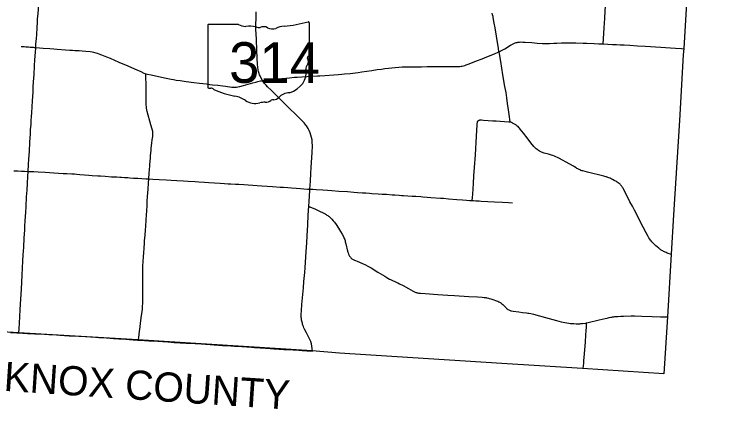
# Model space of a CAD drawing. Extents: x 1815539 to 1947826, y 273303 to 993194.
# Drawn here: x 1905397 to 1929509, y 852982 to 866502 of the extents above; entities that cross this region are included whole.
import ezdxf

# ---------------------------------------------------------------- set-up
doc = ezdxf.new("R2010")
doc.units = 0
for name, color, linetype in [('GM_X_Adjacent_County_Text', 7, 'Continuous'), ('GM_X_County', 7, 'Continuous'), ('GM_X_County_Road', 7, 'Continuous'), ('GM_X_State_Route', 7, 'Continuous'), ('GM_X_Township_Road', 7, 'Continuous'), ('SC_Shading3', 7, 'Continuous')]:
    doc.layers.add(name, color=color, linetype=linetype)

msp = doc.modelspace()

# ---------------------------------------------------------------- linework, layer by layer
at = {"layer": 'GM_X_County'}
msp.add_lwpolyline([(1929509, 885709), (1929483, 885147), (1929313, 880637), (1929312, 880613), (1928987, 876105), (1928954, 875572), (1928932, 875213), (1928849, 873883), (1928341, 865325), (1928314, 865105), (1928189, 862861), (1927988, 859624), (1927907, 858279), (1927777, 856135), (1927658, 854184), (1924873, 854361), (1922111, 854537), (1916549, 854893), (1915609, 854967), (1909640, 855342), (1905546, 855583), (1900992, 855867)], dxfattribs=at)
at = {"layer": 'GM_X_County_Road'}
for points in [[(1925577, 865482), (1925590, 865650), (1925613, 866026), (1925635, 866353), (1925651, 866614), (1925660, 866761), (1925672, 866958), (1925687, 867219), (1925706, 867530), (1925716, 867693), (1925727, 867873), (1925743, 868135), (1925765, 868478), (1925780, 868739), (1925793, 868952), (1925813, 869262), (1925827, 869476)], [(1906139, 865355), (1906148, 865479), (1906161, 865659), (1906173, 865815), (1906185, 866019), (1906199, 866231), (1906205, 866329), (1906219, 866526), (1906230, 866675), (1906238, 866822), (1906244, 866918), (1906256, 867164), (1906266, 867327), (1906272, 867458), (1906276, 867540), (1906279, 867576)], [(1922010, 865208), (1922119, 865267), (1922208, 865315), (1922405, 865433), (1922477, 865473), (1922535, 865502), (1922565, 865515), (1922596, 865526), (1922628, 865534), (1922660, 865540), (1922710, 865545), (1922759, 865547), (1922825, 865545), (1922907, 865541), (1923136, 865524), (1923316, 865511), (1923496, 865498), (1923611, 865492), (1923682, 865490), (1923742, 865492), (1923890, 865501), (1923988, 865506), (1924147, 865514), (1924152, 865514), (1924284, 865520), (1924415, 865522), (1924514, 865522), (1924645, 865518), (1924891, 865509), (1925022, 865505), (1925268, 865495), (1925429, 865488), (1925577, 865482)], [(1925577, 865482), (1925894, 865465), (1926038, 865458), (1926161, 865452), (1926248, 865446), (1926301, 865444), (1926495, 865433), (1926757, 865417), (1927018, 865401), (1927555, 865366), (1927718, 865355), (1928054, 865333), (1928259, 865318), (1928358, 865310)], [(1905878, 861113), (1905895, 861355), (1905906, 861535), (1905921, 861797), (1905939, 862119), (1905957, 862403), (1905965, 862534), (1905977, 862730), (1905986, 862861), (1905993, 862992), (1906002, 863123), (1906029, 863532), (1906038, 863679), (1906046, 863827), (1906056, 864007), (1906068, 864187), (1906081, 864432), (1906084, 864514), (1906092, 864645), (1906097, 864743), (1906108, 864923), (1906119, 865070), (1906129, 865201), (1906138, 865332), (1906139, 865355)], [(1920339, 864710), (1920454, 864709), (1920601, 864708), (1920666, 864710), (1920715, 864715), (1920747, 864720), (1920795, 864730), (1920842, 864743), (1920889, 864759), (1920950, 864782), (1921102, 864843), (1921240, 864897), (1921428, 864970), (1921591, 865034), (1921851, 865137), (1922006, 865206), (1922010, 865208)], [(1913907, 864224), (1913965, 864232), (1914021, 864238), (1914567, 864294), (1914828, 864323), (1915008, 864339), (1915090, 864346), (1915254, 864354), (1915614, 864373), (1915794, 864385), (1915876, 864390), (1916040, 864402), (1916351, 864423), (1916515, 864435), (1916629, 864444), (1916711, 864451), (1916907, 864469), (1917004, 864480), (1917183, 864504), (1917313, 864522), (1917476, 864546), (1917654, 864573), (1917833, 864599), (1917979, 864620), (1918093, 864635), (1918223, 864653), (1918337, 864666), (1918452, 864678), (1918583, 864687), (1918697, 864693), (1918845, 864697), (1919058, 864700), (1919190, 864700), (1919354, 864700), (1919551, 864703), (1919879, 864707), (1920043, 864711), (1920191, 864711), (1920339, 864710)], [(1905393, 861139), (1905528, 861131), (1905646, 861126), (1905759, 861120), (1905878, 861113)], [(1905558, 855587), (1905569, 855740), (1905581, 855920), (1905607, 856378), (1905629, 856755), (1905638, 856902), (1905649, 857098), (1905659, 857311), (1905673, 857573), (1905685, 857803), (1905701, 858048), (1905712, 858247), (1905728, 858523), (1905746, 858834), (1905761, 859112), (1905769, 859243), (1905779, 859424), (1905789, 859571), (1905796, 859718), (1905807, 859898), (1905828, 860242), (1905835, 860356), (1905841, 860471), (1905854, 860717), (1905867, 860946), (1905878, 861110), (1905878, 861113)], [(1905878, 861113), (1905907, 861112), (1906070, 861106), (1906219, 861099), (1906460, 861085), (1906607, 861075), (1906762, 861065), (1906918, 861053), (1907080, 861046), (1907206, 861041), (1907376, 861036), (1907470, 861029), (1907546, 861019), (1907650, 861006), (1907804, 860992), (1907963, 860983), (1908077, 860976), (1908264, 860965), (1908355, 860959), (1908522, 860947), (1908732, 860932), (1908922, 860924), (1909017, 860919), (1909081, 860914), (1909176, 860908), (1909292, 860901), (1909358, 860897), (1909485, 860888), (1909639, 860879), (1909776, 860872), (1909916, 860863), (1910012, 860858)], [(1910012, 860858), (1910156, 860849), (1910364, 860840), (1910612, 860828), (1910776, 860818), (1910972, 860805), (1911201, 860789), (1911366, 860779), (1911605, 860766), (1911723, 860758), (1911923, 860745), (1912071, 860735), (1912453, 860712), (1912603, 860701), (1912736, 860694), (1912822, 860688), (1912986, 860680), (1913100, 860673), (1913264, 860663), (1913411, 860653), (1913886, 860622), (1914246, 860597), (1914508, 860579), (1914622, 860571), (1914770, 860562), (1914904, 860551), (1915061, 860538), (1915211, 860528), (1915321, 860518), (1915444, 860511), (1915533, 860508)], [(1915496, 859920), (1915526, 859907), (1915720, 859818), (1915883, 859740), (1915958, 859705), (1916005, 859683), (1916050, 859660), (1916069, 859649), (1916089, 859638), (1916116, 859622), (1916141, 859606), (1916167, 859587), (1916192, 859566), (1916217, 859544), (1916242, 859522), (1916283, 859480), (1916332, 859427), (1916353, 859403), (1916374, 859376), (1916431, 859295), (1916510, 859171), (1916579, 859059), (1916639, 858962), (1916678, 858889), (1916697, 858848), (1916710, 858818), (1916723, 858783), (1916734, 858744), (1916745, 858704), (1916760, 858640), (1916819, 858386), (1916829, 858353), (1916837, 858323), (1916855, 858277), (1916865, 858257), (1916877, 858234), (1916890, 858214), (1916906, 858191), (1916921, 858174), (1916937, 858158), (1916973, 858126), (1917013, 858099), (1917037, 858085), (1917059, 858075), (1917093, 858061), (1917146, 858039), (1917329, 857967), (1917434, 857921), (1917521, 857875), (1917634, 857808), (1917857, 857669), (1918095, 857523), (1918199, 857462), (1918259, 857429), (1918295, 857410), (1918336, 857390), (1918382, 857368), (1918421, 857351), (1918463, 857334), (1918507, 857315), (1918549, 857296), (1918603, 857268), (1918721, 857208), (1918908, 857105), (1919066, 857019), (1919110, 856995), (1919139, 856983), (1919161, 856973), (1919184, 856966), (1919207, 856960), (1919232, 856955), (1919263, 856950), (1919287, 856947), (1919324, 856942), (1919476, 856929), (1919918, 856902), (1920262, 856879), (1920490, 856865), (1920981, 856834), (1921276, 856817), (1921437, 856807), (1921499, 856802), (1921533, 856798), (1921557, 856795), (1921582, 856790), (1921608, 856784), (1921647, 856775), (1921678, 856768), (1921731, 856751), (1921803, 856727), (1921926, 856681), (1921967, 856666), (1922003, 856651), (1922024, 856641), (1922047, 856629), (1922067, 856615), (1922089, 856602), (1922110, 856586), (1922139, 856559), (1922186, 856512), (1922231, 856465), (1922255, 856442), (1922272, 856425), (1922287, 856411), (1922302, 856401), (1922316, 856390), (1922347, 856372), (1922368, 856361), (1922389, 856351), (1922412, 856342), (1922435, 856336), (1922499, 856324), (1922691, 856301), (1922818, 856287), (1922957, 856271), (1922997, 856266), (1923035, 856261), (1923095, 856250), (1923191, 856227), (1923602, 856114), (1923981, 856009), (1924139, 855967), (1924268, 855939), (1924334, 855928), (1924397, 855919), (1924462, 855912), (1924511, 855907), (1924578, 855902), (1924658, 855899), (1924740, 855899), (1924776, 855900), (1924815, 855902), (1924870, 855907), (1924983, 855923), (1925012, 855929)], [(1925012, 855929), (1925061, 855938), (1925443, 856031), (1925650, 856081), (1925712, 856094), (1925780, 856110), (1925843, 856122), (1925867, 856126), (1925899, 856132), (1925940, 856138), (1925979, 856143), (1926013, 856146), (1926082, 856151), (1926181, 856157), (1926279, 856161), (1926541, 856170), (1926654, 856169), (1926907, 856160), (1927262, 856148), (1927540, 856139), (1927711, 856134), (1927729, 856133), (1927751, 856132), (1927784, 856130)], [(1905275, 855603), (1905405, 855595), (1905488, 855590), (1905558, 855587)]]:
    msp.add_lwpolyline(points, dxfattribs=at)
at = {"layer": 'GM_X_State_Route'}
msp.add_lwpolyline([(1915617, 854964), (1915613, 855047), (1915603, 855128), (1915585, 855208), (1915561, 855287), (1915531, 855363), (1915489, 855453), (1915420, 855583), (1915351, 855713), (1915329, 855764), (1915310, 855807), (1915294, 855851), (1915282, 855888), (1915273, 855919), (1915262, 855958), (1915249, 856019), (1915245, 856044), (1915240, 856078), (1915237, 856114), (1915234, 856152), (1915232, 856217), (1915239, 856348), (1915260, 856559), (1915279, 856788), (1915309, 857131), (1915327, 857343), (1915353, 857652), (1915365, 857816), (1915404, 858372), (1915421, 858666), (1915435, 858912), (1915456, 859288), (1915476, 859615), (1915496, 859920), (1915507, 860090), (1915530, 860466), (1915533, 860508), (1915549, 860777), (1915564, 861039), (1915578, 861251), (1915606, 861759), (1915615, 861988), (1915614, 862119), (1915605, 862201), (1915589, 862281), (1915567, 862361), (1915539, 862438), (1915506, 862514), (1915467, 862586), (1915415, 862670), (1915394, 862700), (1915371, 862730), (1915331, 862777), (1915301, 862810), (1915266, 862847), (1915163, 862951), (1915022, 863088), (1914858, 863249), (1914692, 863408), (1914201, 863891), (1914076, 864015), (1914028, 864065), (1913974, 864126), (1913926, 864192), (1913907, 864224), (1913893, 864248), (1913848, 864336), (1913822, 864391), (1913809, 864425), (1913795, 864464), (1913783, 864502), (1913772, 864539), (1913763, 864582), (1913755, 864620), (1913749, 864662), (1913745, 864696), (1913740, 864760), (1913716, 865251), (1913699, 865644), (1913684, 865988), (1913681, 866151), (1913685, 866348), (1913693, 866577)], dxfattribs=at)
at = {"layer": 'GM_X_Township_Road'}
for points in [[(1922010, 865208), (1922009, 865215), (1921988, 865321), (1921920, 865751), (1921874, 866026), (1921846, 866187), (1921813, 866381), (1921805, 866420), (1921792, 866478), (1921774, 866538)], [(1905640, 865396), (1905666, 865393)], [(1905666, 865393), (1905673, 865392), (1905700, 865389), (1905737, 865387), (1905799, 865383), (1905889, 865377), (1905948, 865374), (1905998, 865370), (1906052, 865364), (1906081, 865362), (1906103, 865360), (1906121, 865358), (1906131, 865356), (1906139, 865355)], [(1906139, 865355), (1906388, 865333), (1906617, 865318), (1906764, 865309), (1906878, 865302), (1907155, 865282), (1907302, 865272), (1907400, 865265), (1907482, 865260), (1907629, 865250), (1907727, 865242), (1907857, 865230), (1908004, 865216), (1908069, 865207), (1908118, 865198), (1908197, 865178), (1908244, 865163), (1908306, 865141), (1908397, 865104), (1908564, 865036), (1908685, 864987), (1908836, 864923), (1908986, 864858), (1909122, 864802), (1909213, 864763), (1909393, 864684), (1909527, 864624), (1909737, 864531), (1909844, 864484), (1909910, 864456)], [(1922392, 862807), (1922355, 863065), (1922333, 863228), (1922304, 863439), (1922277, 863634), (1922250, 863812), (1922214, 864022), (1922146, 864426), (1922067, 864878), (1922021, 865137), (1922010, 865208)], [(1909921, 863493), (1909921, 863590), (1909922, 863719), (1909921, 863913), (1909919, 864120), (1909912, 864312), (1909910, 864456)], [(1909910, 864456), (1909968, 864443), (1910088, 864417), (1910246, 864382), (1910400, 864349), (1910552, 864319), (1910778, 864273), (1910858, 864258), (1910955, 864242), (1911085, 864225), (1911296, 864197), (1911556, 864161), (1911751, 864138), (1911864, 864122), (1911985, 864108), (1912105, 864095), (1912197, 864083), (1912374, 864063), (1912548, 864042), (1912645, 864030), (1912856, 864000), (1912905, 863996), (1912937, 863995), (1912969, 863995), (1913018, 864000), (1913066, 864009), (1913129, 864025), (1913255, 864060), (1913572, 864145), (1913682, 864176), (1913752, 864194), (1913791, 864202), (1913837, 864212), (1913877, 864219), (1913907, 864224)], [(1910045, 861283), (1910049, 861340), (1910058, 861464), (1910068, 861570), (1910075, 861651), (1910083, 861753), (1910091, 861836), (1910099, 861907), (1910115, 862082), (1910132, 862197), (1910146, 862309), (1910154, 862398), (1910153, 862439), (1910146, 862482), (1910122, 862560), (1910078, 862713), (1909959, 863171), (1909932, 863283), (1909923, 863440), (1909922, 863456), (1909921, 863493)], [(1921094, 860120), (1921104, 860216), (1921112, 860330), (1921135, 860705), (1921152, 860966), (1921171, 861244), (1921201, 861684), (1921241, 862320), (1921263, 862713), (1921266, 862758), (1921267, 862772), (1921269, 862789), (1921271, 862800), (1921272, 862806), (1921274, 862813), (1921276, 862819), (1921279, 862826), (1921285, 862834), (1921290, 862841), (1921295, 862846), (1921300, 862851), (1921307, 862857), (1921313, 862861), (1921321, 862865), (1921328, 862868), (1921335, 862871), (1921343, 862874), (1921351, 862876), (1921358, 862877), (1921368, 862878), (1921376, 862879), (1921388, 862879), (1921409, 862878), (1921474, 862874), (1921799, 862849), (1921914, 862841), (1922045, 862833), (1922351, 862813), (1922364, 862812), (1922377, 862810), (1922392, 862807)], [(1927917, 858265), (1927841, 858291), (1927772, 858318), (1927735, 858334), (1927650, 858375), (1927621, 858390), (1927590, 858407), (1927565, 858422), (1927540, 858438), (1927523, 858451), (1927481, 858484), (1927431, 858527), (1927383, 858570), (1927318, 858631), (1927277, 858671), (1927248, 858701), (1927222, 858732), (1927199, 858761), (1927172, 858797), (1927143, 858843), (1927121, 858881), (1927050, 859011), (1926850, 859399), (1926753, 859589), (1926647, 859793), (1926578, 859922), (1926497, 860072), (1926420, 860216), (1926287, 860480), (1926258, 860538), (1926244, 860564), (1926232, 860584), (1926221, 860602), (1926206, 860623), (1926197, 860635), (1926187, 860647), (1926176, 860658), (1926160, 860675), (1926144, 860689), (1926127, 860703), (1926111, 860714), (1926094, 860725), (1926058, 860749), (1926032, 860765), (1925959, 860806), (1925897, 860838), (1925857, 860858), (1925813, 860879), (1925767, 860897), (1925733, 860910), (1925690, 860925), (1925665, 860933), (1925596, 860952), (1925038, 861090), (1924878, 861129), (1924845, 861140), (1924816, 861150), (1924783, 861163), (1924756, 861176), (1924713, 861198), (1924677, 861218), (1924649, 861235), (1924599, 861266), (1924557, 861291), (1924415, 861373), (1924085, 861556), (1924012, 861593), (1923955, 861619), (1923906, 861639), (1923859, 861656), (1923813, 861671), (1923702, 861703), (1923561, 861745), (1923469, 861778), (1923423, 861797), (1923397, 861811), (1923366, 861829), (1923336, 861849), (1923313, 861867), (1923285, 861890), (1923263, 861910), (1923208, 861970), (1923104, 862098), (1922971, 862264), (1922851, 862421), (1922739, 862562), (1922709, 862598), (1922685, 862623), (1922662, 862647), (1922637, 862669), (1922618, 862684), (1922598, 862699), (1922581, 862710), (1922558, 862724), (1922539, 862735), (1922520, 862745), (1922472, 862771), (1922440, 862787), (1922420, 862796), (1922407, 862801), (1922392, 862807)], [(1910012, 860858), (1910014, 860883), (1910026, 861029), (1910039, 861193), (1910045, 861283)], [(1909805, 856847), (1909805, 856849), (1909810, 857145), (1909813, 857342), (1909811, 857463), (1909811, 857571), (1909809, 857667), (1909807, 857752), (1909807, 857794), (1909809, 857855), (1909810, 857887), (1909819, 858017), (1909833, 858197), (1909843, 858328), (1909854, 858492), (1909864, 858655), (1909870, 858737), (1909878, 858835), (1909884, 858917), (1909898, 859114), (1909906, 859228), (1909922, 859457), (1909933, 859621), (1909943, 859769), (1909952, 859943), (1909961, 860092), (1909971, 860256), (1909979, 860385), (1909985, 860504), (1910000, 860707), (1910012, 860858)], [(1915533, 860508), (1915562, 860508), (1915627, 860506), (1915741, 860499), (1915970, 860484), (1916134, 860473), (1916281, 860463), (1916527, 860443), (1916822, 860422), (1917035, 860406), (1917166, 860396), (1917329, 860383), (1917444, 860376), (1917575, 860369), (1917657, 860364), (1917866, 860349), (1918006, 860340), (1918151, 860330), (1918347, 860316), (1918444, 860310), (1918591, 860299), (1918673, 860294), (1918739, 860289), (1918886, 860280), (1919033, 860271), (1919164, 860262), (1919327, 860251), (1919403, 860246), (1919547, 860236), (1919678, 860226), (1920005, 860200), (1920109, 860193), (1920283, 860178), (1920562, 860157), (1920758, 860142), (1920892, 860132), (1921004, 860124), (1921094, 860120)], [(1921094, 860120), (1921133, 860117), (1921215, 860112), (1921275, 860107), (1921332, 860103), (1921401, 860100), (1921858, 860078), (1922127, 860060), (1922335, 860045), (1922475, 860036)], [(1909702, 855702), (1909716, 855804), (1909728, 855902), (1909754, 856097), (1909764, 856178), (1909780, 856309), (1909791, 856407), (1909800, 856505), (1909804, 856587), (1909805, 856669), (1909804, 856718), (1909805, 856847)], [(1924892, 854363), (1924910, 854552), (1924919, 854646), (1924928, 854728), (1924951, 855019), (1924960, 855121), (1924964, 855169), (1924968, 855247), (1924971, 855299), (1924981, 855480), (1925001, 855692), (1925006, 855752), (1925010, 855823), (1925010, 855849), (1925011, 855905), (1925012, 855929)], [(1905558, 855587), (1905695, 855578), (1905859, 855569), (1906104, 855555), (1906437, 855537), (1906585, 855530), (1906699, 855525), (1906856, 855514), (1906960, 855507), (1907282, 855488), (1907610, 855470), (1907839, 855457), (1908019, 855447), (1908182, 855436), (1908297, 855429), (1908559, 855411), (1908689, 855403), (1908804, 855396), (1908984, 855385), (1909229, 855370), (1909474, 855353), (1909637, 855341), (1909654, 855341)], [(1909654, 855341), (1909658, 855364), (1909667, 855429), (1909694, 855641), (1909702, 855702)], [(1909654, 855341), (1909719, 855337), (1909866, 855329), (1910014, 855319), (1910178, 855310), (1910325, 855298), (1910497, 855288), (1910668, 855276), (1910887, 855260), (1911090, 855247), (1911290, 855235), (1911596, 855218), (1911807, 855205), (1911953, 855197), (1912117, 855186), (1912256, 855177), (1912403, 855167), (1912534, 855157), (1912681, 855148), (1912943, 855131), (1913205, 855114), (1913368, 855104), (1913532, 855092), (1913630, 855086), (1913728, 855080), (1913827, 855075), (1913908, 855070), (1914006, 855063), (1914105, 855057), (1914170, 855052), (1914301, 855044), (1914480, 855032), (1914639, 855021), (1914808, 855012), (1914961, 855002), (1915152, 854990), (1915266, 854983), (1915430, 854973), (1915512, 854968), (1915617, 854964)]]:
    msp.add_lwpolyline(points, dxfattribs=at)
at = {"layer": 'SC_Shading3'}
for p, q in [((1913085, 866148), (1912066, 866148)), ((1915512, 865095), (1915512, 866200)), ((1912031, 866111), (1912031, 863998)), ((1915512, 865095), (1915512, 865095))]:
    msp.add_line(p, q, dxfattribs=at)
for centre, major_axis, start_param, end_param in [((1912071, 866116), (40.3, 0), 1.712693, 3.28349), ((1913328, 866393), (391, 0), 4.042523, 4.731795), ((1914272, 869029), (3691, 0), 4.814394, 5.042369), ((1915473, 866205), (38.7, 0), 6.141152, 7.989035), ((1913457, 864961), (1404, 0), 1.404758, 1.657858), ((1913776, 866127), (113, 0), 3.836095, 5.185415), ((1913942, 865883), (235, 0), 0.950623, 2.079405), ((1914245, 866218), (282, 0), 4.081561, 5.145723), ((1914743, 865502), (743, 0), 1.699011, 2.107814), ((1915503, 865013), (60, 0), 1.883978, 3.671073), ((1915121, 864874), (360, 0), 5.934695, 6.695948), ((1915471, 865090), (41.5, 0), 5.05454, 6.418171), ((1915651, 864632), (262, 0), 2.387724, 3.262537), ((1914479, 864491), (923, 0), 5.101752, 6.440018), ((1912072, 863993), (40.7, 0), 3.00124, 4.508301), ((1912078, 864210), (310, 0), 4.665946, 4.897461), ((1912141, 863876), (112, 0), 0.519207, 1.627899), ((1913555, 865775), (2665, 0), 4.195997, 4.488961), ((1914868, 863405), (506, 0), 1.647645, 2.488434), ((1912760, 863049), (834, 0), 0.823519, 1.323587), ((1913662, 863866), (529, 0), 4.026481, 4.996735), ((1913968, 863135), (435, 0), 1.495662, 1.94098), ((1914006, 863707), (282, 0), 4.691044, 5.507374), ((1914261, 863503), (79.4, 0), 1.147584, 2.315152), ((1914228, 863793), (298, 0), 4.937069, 5.64225)]:
    msp.add_ellipse(centre, major_axis=major_axis, ratio=0.8, start_param=start_param, end_param=end_param, dxfattribs=at)

# ---------------------------------------------------------------- texts
at = {"layer": 'GM_X_Adjacent_County_Text'}
msp.add_text('KNOX COUNTY', height=1000, rotation=356.2231, dxfattribs=at).set_placement((1905024, 853603))
at = {"layer": 'SC_Shading3'}
msp.add_text('314', height=1392.2, dxfattribs=at).set_placement((1912765, 864147))

doc.saveas('drawing.dxf')
